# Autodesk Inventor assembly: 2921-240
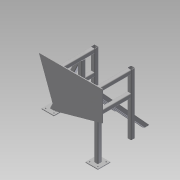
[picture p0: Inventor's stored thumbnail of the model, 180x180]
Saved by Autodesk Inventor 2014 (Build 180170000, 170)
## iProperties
Company: NHTSA/VRTC
Created: 2012-02
Part Number: 2921-240
Document SubType Name: Assembly
Designer: Mike Vanvooris
Project: CHILD SIDE IMPACT SLED
Description: IMPACTOR FRAME ASSEMBLY
Mass: 66982.5 g
Surface Area: 40098.8 cm^2
Volume: 8532.8 cm^3
Density: 7.85 g/cm^3
Title: IMPACTOR FRAME ASSEMBLY
Subject: Child Side Impact Sled
Author: Dave Walker
Revision Number: A
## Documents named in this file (11)
- B:\VRTC_DWG\BIO\Non-P572\Child Side-Frontal Impact Sled\Side Impact Sled\Impactor_Frame_Assembly_4.iam
- B:\VRTC_DWG\BIO\Non-P572\Child Side-Frontal Impact Sled\Side Impact Sled\Impactor_Frame_Tube_1.ipt
- B:\VRTC_DWG\BIO\Non-P572\Child Side-Frontal Impact Sled\Side Impact Sled\Impactor_Frame_Tube-3.ipt
- B:\VRTC_DWG\BIO\Non-P572\Child Side-Frontal Impact Sled\Side Impact Sled\Impactor_Frame_Tube-2.ipt
- B:\VRTC_DWG\BIO\Non-P572\Child Side-Frontal Impact Sled\Side Impact Sled\Impactor_Frame_Tube-4.ipt
- B:\VRTC_DWG\BIO\Non-P572\Child Side-Frontal Impact Sled\Side Impact Sled\Impactor_Frame_Tube-5.ipt
- B:\VRTC_DWG\BIO\Non-P572\Child Side-Frontal Impact Sled\Side Impact Sled\Impactor_Frame_Tube-7.ipt
- B:\VRTC_DWG\BIO\Non-P572\Child Side-Frontal Impact Sled\Side Impact Sled\Impactor_Frame_Tube-8.ipt
- B:\VRTC_DWG\BIO\Non-P572\Child Side-Frontal Impact Sled\Side Impact Sled\Impactor_Door_Plate.ipt
- B:\VRTC_DWG\BIO\Non-P572\Child Side-Frontal Impact Sled\Side Impact Sled\Impactor_Frame_Tube-6.ipt
- B:\VRTC_DWG\BIO\Non-P572\Child Side-Frontal Impact Sled\Side Impact Sled\Impactor_Support_Plate.ipt
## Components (19 placed, 10 different names)
1. Impactor_Support_Plate:1 — Flush:37, Mate:30, Mate:31, Mate:32, Mate:33
2. Impactor_Support_Plate:2 — Flush:37, Mate:36
3. Impactor_Frame_Tube_1:1 — Mate:5, Flush:6, Mate:25, Flush:36
4. Impactor_Frame_Tube-3:1 — Mate:5, Flush:6, Flush:7, Mate:7, Flush:8, Flush:9, Mate:8, Flush:10, Flush:11, Flush:21, Mate:12, Flush:22, Mate:13, Flush:23, Flush:24, Flush:13, Flush:38
5. Impactor_Frame_Tube-2:1 — Flush:7, Mate:14, Flush:25, Mate:30
6. Impactor_Frame_Tube-4:1 — Mate:7, Flush:8, Flush:9, Mate:9, Flush:12, Flush:13, Mate:19, Mate:21, Mate:22
7. Impactor_Frame_Tube-4:2 — Mate:8, Flush:10, Flush:11
8. Impactor_Frame_Tube-3:2 — Mate:9, Flush:12, Mate:10, Flush:14, Flush:15, Mate:11, Flush:16, Flush:17, Flush:38
9. Impactor_Frame_Tube-5:1 — Flush:21, Mate:12, Flush:22
10. Impactor_Frame_Tube-5:2 — Mate:13, Flush:23, Flush:24, Mate:14, Flush:25, Mate:34
11. Impactor_Frame_Tube-5:3 — Mate:11, Flush:16, Flush:17, Mate:28
12. Impactor_Frame_Tube-5:4 — Mate:10, Flush:14, Flush:15, Flush:26, Mate:16, Mate:17, Flush:33, Flush:35
13. Impactor_Frame_Tube-2:2 — Flush:26, Mate:16, Flush:35, Mate:36
14. Impactor_Frame_Tube-7:1 — Mate:17, Flush:34, Mate:35
15. Impactor_Frame_Tube-8:1 — Mate:21, Flush:29, Flush:30, Mate:31, Mate:34
16. Impactor_Frame_Tube-8:2 — Mate:19, Flush:29, Mate:32
17. Impactor_Frame_Tube-8:3 — Mate:22, Flush:30, Mate:33
18. Impactor_Door_Plate:1 — Mate:25, Flush:36, Mate:35
19. Impactor_Frame_Tube-6:1 — Flush:33, Flush:34, Mate:28
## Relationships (49: Flush 26, Mate 23)
- Mate:5: Impactor_Frame_Tube_1:1 ↔ Impactor_Frame_Tube-3:1
- Flush:6: Impactor_Frame_Tube_1:1 ↔ Impactor_Frame_Tube-3:1
- Flush:7: Impactor_Frame_Tube-3:1 ↔ Impactor_Frame_Tube-2:1
- Mate:7: Impactor_Frame_Tube-3:1 ↔ Impactor_Frame_Tube-4:1
- Flush:8: Impactor_Frame_Tube-3:1 ↔ Impactor_Frame_Tube-4:1
- Flush:9: Impactor_Frame_Tube-3:1 ↔ Impactor_Frame_Tube-4:1
- Mate:8: Impactor_Frame_Tube-3:1 ↔ Impactor_Frame_Tube-4:2
- Flush:10: Impactor_Frame_Tube-3:1 ↔ Impactor_Frame_Tube-4:2
- Flush:11: Impactor_Frame_Tube-3:1 ↔ Impactor_Frame_Tube-4:2
- Mate:9: Impactor_Frame_Tube-4:1 ↔ Impactor_Frame_Tube-3:2
- Flush:12: Impactor_Frame_Tube-4:1 ↔ Impactor_Frame_Tube-3:2
- Flush:13: Impactor_Frame_Tube-3:1 ↔ Impactor_Frame_Tube-4:1
- Mate:10: Impactor_Frame_Tube-3:2 ↔ Impactor_Frame_Tube-5:4
- Flush:14: Impactor_Frame_Tube-3:2 ↔ Impactor_Frame_Tube-5:4
- Flush:15: Impactor_Frame_Tube-3:2 ↔ Impactor_Frame_Tube-5:4
- Mate:11: Impactor_Frame_Tube-3:2 ↔ Impactor_Frame_Tube-5:3
- Flush:16: Impactor_Frame_Tube-3:2 ↔ Impactor_Frame_Tube-5:3
- Flush:17: Impactor_Frame_Tube-3:2 ↔ Impactor_Frame_Tube-5:3
- Flush:21: Impactor_Frame_Tube-3:1 ↔ Impactor_Frame_Tube-5:1
- Mate:12: Impactor_Frame_Tube-3:1 ↔ Impactor_Frame_Tube-5:1
- Flush:22: Impactor_Frame_Tube-3:1 ↔ Impactor_Frame_Tube-5:1
- Mate:13: Impactor_Frame_Tube-3:1 ↔ Impactor_Frame_Tube-5:2
- Flush:23: Impactor_Frame_Tube-3:1 ↔ Impactor_Frame_Tube-5:2
- Flush:24: Impactor_Frame_Tube-3:1 ↔ Impactor_Frame_Tube-5:2
- Mate:14: Impactor_Frame_Tube-2:1 ↔ Impactor_Frame_Tube-5:2
- Flush:25: Impactor_Frame_Tube-2:1 ↔ Impactor_Frame_Tube-5:2
- Flush:26: Impactor_Frame_Tube-5:4 ↔ Impactor_Frame_Tube-2:2
- Mate:16: Impactor_Frame_Tube-5:4 ↔ Impactor_Frame_Tube-2:2
- Mate:17: Impactor_Frame_Tube-5:4 ↔ Impactor_Frame_Tube-7:1
- Mate:19: Impactor_Frame_Tube-4:1 ↔ Impactor_Frame_Tube-8:2
- Mate:21: Impactor_Frame_Tube-4:1 ↔ Impactor_Frame_Tube-8:1
- Mate:22: Impactor_Frame_Tube-4:1 ↔ Impactor_Frame_Tube-8:3
- Flush:29: Impactor_Frame_Tube-8:1 ↔ Impactor_Frame_Tube-8:2
- Flush:30: Impactor_Frame_Tube-8:1 ↔ Impactor_Frame_Tube-8:3
- Mate:25: Impactor_Frame_Tube_1:1 ↔ Impactor_Door_Plate:1
- Flush:33: Impactor_Frame_Tube-5:4 ↔ Impactor_Frame_Tube-6:1
- Flush:34: Impactor_Frame_Tube-7:1 ↔ Impactor_Frame_Tube-6:1
- Flush:35: Impactor_Frame_Tube-5:4 ↔ Impactor_Frame_Tube-2:2
- Mate:28: Impactor_Frame_Tube-5:3 ↔ Impactor_Frame_Tube-6:1
- Flush:36: Impactor_Frame_Tube_1:1 ↔ Impactor_Door_Plate:1
- Flush:37: Impactor_Support_Plate:1 ↔ Impactor_Support_Plate:2
- Mate:30: Impactor_Support_Plate:1 ↔ Impactor_Frame_Tube-2:1
- Flush:38: Impactor_Frame_Tube-3:1 ↔ Impactor_Frame_Tube-3:2
- Mate:31: Impactor_Support_Plate:1 ↔ Impactor_Frame_Tube-8:1
- Mate:32: Impactor_Support_Plate:1 ↔ Impactor_Frame_Tube-8:2
- Mate:33: Impactor_Support_Plate:1 ↔ Impactor_Frame_Tube-8:3
- Mate:34: Impactor_Frame_Tube-5:2 ↔ Impactor_Frame_Tube-8:1
- Mate:35: Impactor_Frame_Tube-7:1 ↔ Impactor_Door_Plate:1
- Mate:36: Impactor_Support_Plate:2 ↔ Impactor_Frame_Tube-2:2
